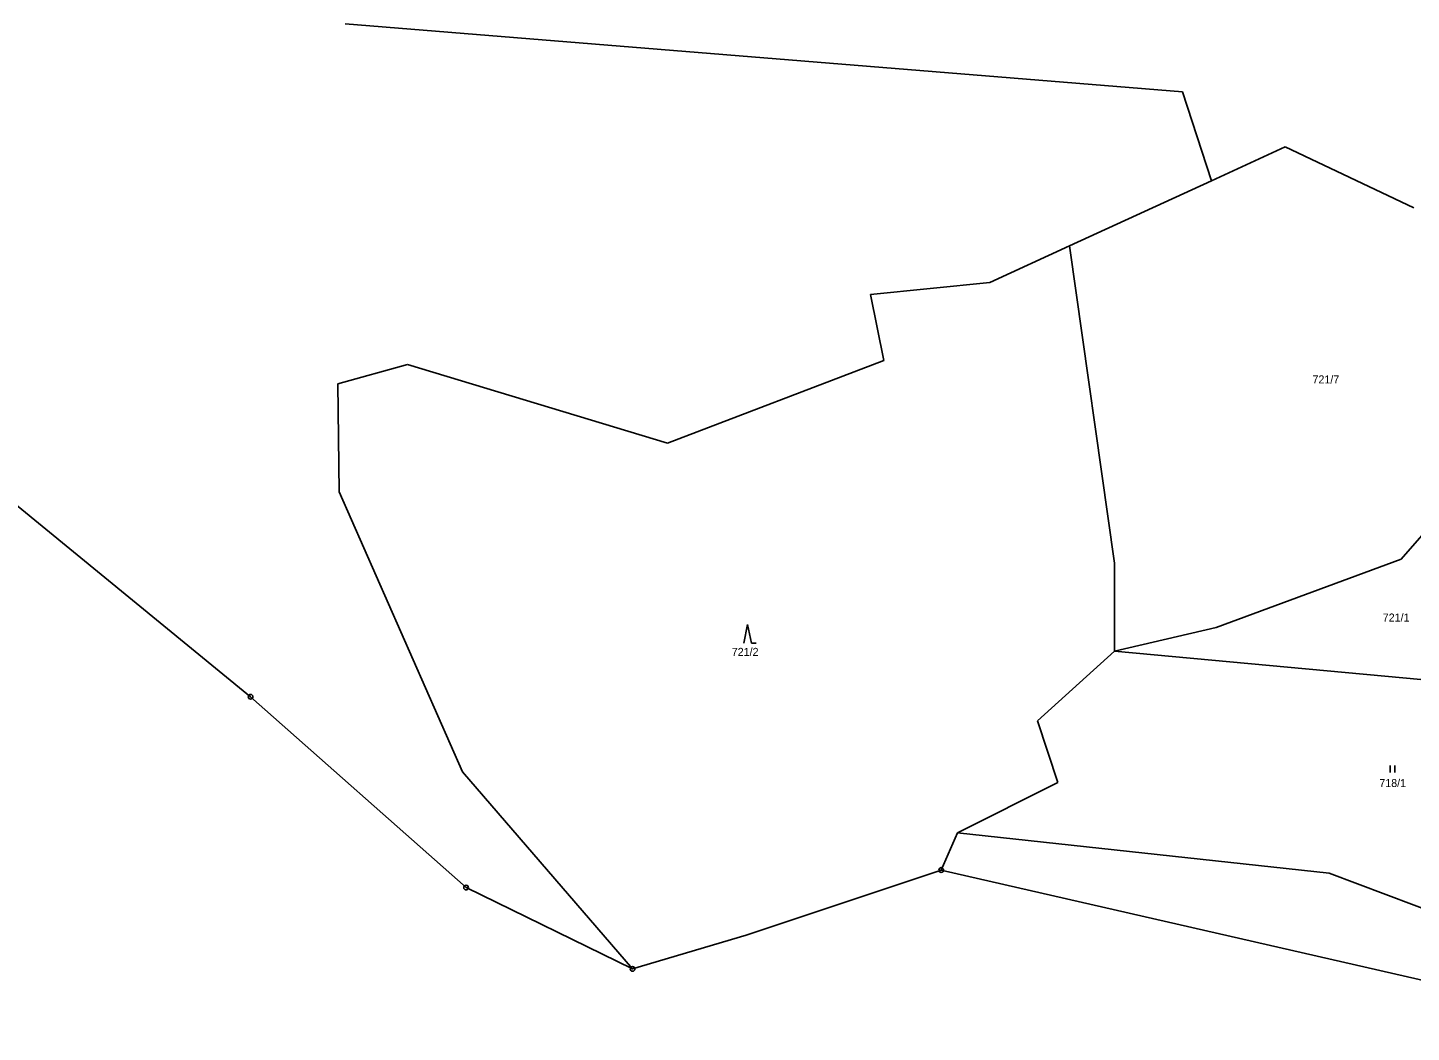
# Model space of a CAD drawing. Extents: x -791032 to -787751, y -1106872 to -1104403.
# Drawn here: x -790290.7 to -789996.7, y -1106573.5 to -1106360.1 of the extents above; entities that cross this region are included whole.
import ezdxf

# ---------------------------------------------------------------- set-up
doc = ezdxf.new("R2010")
doc.units = 0
for name, color, linetype in [('Vrstva 1', 7, 'Continuous'), ('Vrstva 14', 7, 'Continuous'), ('Vrstva 23', 7, 'Continuous'), ('Vrstva 28', 7, 'Continuous'), ('Vrstva 4', 7, 'Continuous')]:
    doc.layers.add(name, color=color, linetype=linetype)

msp = doc.modelspace()

# ---------------------------------------------------------------- linework, layer by layer
at = {"layer": 'Vrstva 1'}
for p, q in [((-790045.36, -1106373.73), (-790223.2, -1106359.24)), ((-790039.19, -1106392.58), (-790045.36, -1106373.73)), ((-790023.52, -1106385.38), (-790039.19, -1106392.58)), ((-789996.22, -1106398.33), (-790023.52, -1106385.38)), ((-790039.19, -1106392.58), (-790069.33, -1106406.42)), ((-790069.33, -1106406.42), (-790086.24, -1106414.19)), ((-790059.79, -1106473.82), (-790069.33, -1106406.42)), ((-790086.24, -1106414.19), (-790111.62, -1106416.76)), ((-790111.62, -1106416.76), (-790108.79, -1106430.76)), ((-790108.79, -1106430.76), (-790154.74, -1106448.38)), ((-790209.95, -1106431.61), (-790224.78, -1106435.76)), ((-790154.74, -1106448.38), (-790209.95, -1106431.61)), ((-790224.78, -1106435.76), (-790224.49, -1106458.69)), ((-789998.89, -1106473.03), (-789984.81, -1106456.85)), ((-790224.49, -1106458.69), (-790198.27, -1106518.16)), ((-790059.77, -1106492.56), (-790059.79, -1106473.82)), ((-790038.15, -1106487.53), (-789998.89, -1106473.03)), ((-790059.77, -1106492.56), (-790038.15, -1106487.53)), ((-790076.15, -1106507.37), (-790059.77, -1106492.56)), ((-790059.77, -1106492.56), (-789986.85, -1106499.32)), ((-790071.8, -1106520.43), (-790076.15, -1106507.37)), ((-790198.27, -1106518.16), (-790162.16, -1106560.06)), ((-790071.8, -1106520.43), (-790093.15, -1106531.17)), ((-790093.15, -1106531.17), (-790096.59, -1106539.05)), ((-790014.2, -1106539.72), (-790093.15, -1106531.17)), ((-790014.2, -1106539.72), (-789963.51, -1106558.79))]:
    msp.add_line(p, q, dxfattribs=at)
at = {"layer": 'Vrstva 23'}
for p, q in [((-790138.51, -1106490.85), (-790137.71, -1106486.85)), ((-790137.71, -1106486.85), (-790136.91, -1106490.85)), ((-790136.91, -1106490.85), (-790135.91, -1106490.85)), ((-790001.23, -1106518.31), (-790001.23, -1106516.81)), ((-790000.23, -1106516.81), (-790000.23, -1106518.31))]:
    msp.add_line(p, q, dxfattribs=at)
at = {"layer": 'Vrstva 28'}
for centre, radius in [((-790243.31, -1106502.23), 0.5), ((-790243.31, -1106502.23), 0.01), ((-790096.59, -1106539.05), 0.5), ((-790096.59, -1106539.05), 0.01), ((-790197.53, -1106542.79), 0.5), ((-790197.53, -1106542.79), 0.01), ((-790162.16, -1106560.06), 0.5), ((-790162.16, -1106560.06), 0.01)]:
    msp.add_circle(centre, radius, dxfattribs=at)
at = {"layer": 'Vrstva 4'}
for p, q in [((-790293.48, -1106461.18), (-790243.31, -1106502.23)), ((-790243.31, -1106502.23), (-790197.53, -1106542.79)), ((-790138.01, -1106552.91), (-790096.59, -1106539.05)), ((-790096.59, -1106539.05), (-789946.3, -1106573.54)), ((-790197.53, -1106542.79), (-790162.16, -1106560.06)), ((-790162.16, -1106560.06), (-790138.01, -1106552.91))]:
    msp.add_line(p, q, dxfattribs=at)

# ---------------------------------------------------------------- texts
at = {"layer": 'Vrstva 14'}
for s, p in [('721/7', (-790017.716, -1106435.65)), ('721/1', (-790002.793, -1106486.25)), ('721/2', (-790141.089, -1106493.55)), ('718/1', (-790003.523, -1106521.42))]:
    msp.add_text(s, height=1.7, dxfattribs=at).set_placement(p)

doc.saveas('drawing.dxf')
